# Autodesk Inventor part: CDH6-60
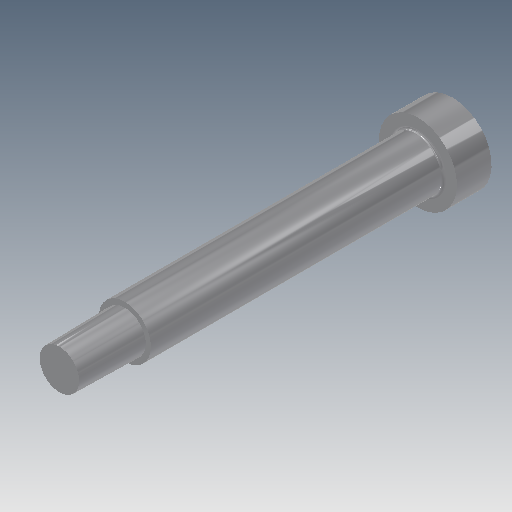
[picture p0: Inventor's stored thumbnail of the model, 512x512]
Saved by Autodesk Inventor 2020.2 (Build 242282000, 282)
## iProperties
Created: 2015-01
Part Number: CDH6-60
Material: Ogólny
Description: Straight Core Pin
Document SubType Name: Modeling
Designer: F.Stasiak
Density: 1 g/cm^3
Appearance: Domyślna
Catalog Web Link: www.expertbooks.pl
Manager: www.cadconsulting.pl
Company: Fabian Stasiak CAD Consulting
Author: F.Stasiak
Subject: Zbiór ćwiczeń. Autodesk Inventor 2020. Kurs Professional
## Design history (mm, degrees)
node "Forma_ZEGAR_260_4_ZEGAR_260_Rdzeń formujący2_Base"
feature "Solid1::Forma_ZEGAR_260_4_ZEGAR_260_Rdzeń formujący2_Base"
tag "Bryła wyprowadzona1"
node "Bryła1"
feature "Forma_ZEGAR_260_4_ZEGAR_260_Rdzeń formujący2_Base_Bodies"
